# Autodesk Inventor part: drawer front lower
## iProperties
Created: 2005-05
Part Number: drawer front lower
Material: mdf
Document SubType Name: Modeling
Designer: a.campbell
Manufacturer: Standard
Standards Organization: Custom
length: 300
thickness: 19
width: 350
Author: a.campbell
Comments: machine to detail
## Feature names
1. Extrusion1
